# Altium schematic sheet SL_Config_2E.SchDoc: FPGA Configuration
size A; Organization: Altium Limited; Address1: L3, 12a Rodborough Rd; Address2: Frenchs Forest; Address3: NSW; Address4: Australia 2086; DocumentNumber: 2; SheetNumber: 2; SheetTotal: 5; Library Name: SpiritLevel_2E.SchLib
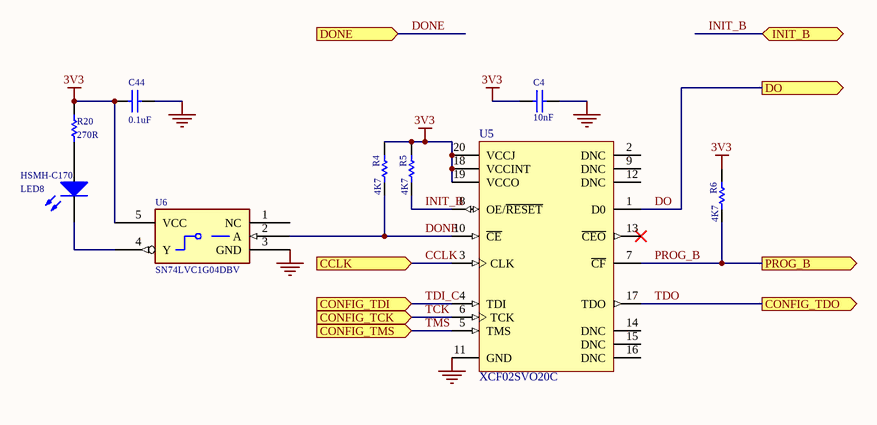
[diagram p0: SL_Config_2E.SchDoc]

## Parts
C4  10nF  [CC1608-0603]
C44  0.1uF  [CC2012-0805]
LED8  HSMH-C170  [SMD _LED]
R4  4K7  [CR2012-0805]
R5  4K7  [CR2012-0805]
R6  4K7  [CR2012-0805]
R20  270R  [CR2012-0805]
U5  XCF02SVO20C  [VO20]
U6  SN74LVC1G04DBV  [SO-G5/P.95]

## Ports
CCLK (in), CONFIG_TCK (in), CONFIG_TDI (in), CONFIG_TDO (out), CONFIG_TMS (in), DO (out), DONE (in), INIT_B (bidir), PROG_B (out)

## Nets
3V3: C4.1 C44.2 R4.1 R5.1 R6.1 R20.2 U5.18(VCCINT) U5.19(VCCO) U5.20(VCCJ) U6.5(VCC)
GND: C4.2 C44.1 U5.11(GND) U6.3(GND)
CCLK: U5.3(CLK) ; port CCLK
DO: U5.1(D0) ; port DO
DONE: R4.2 U5.10(~{CE}) U6.2(A) ; port DONE
INIT_B: R5.2 U5.8(OE/~{RESET}) ; port INIT_B
PROG_B: R6.2 U5.7(~{CF}) ; port PROG_B
TCK: U5.6(TCK) ; port CONFIG_TCK
TDI_C: U5.4(TDI) ; port CONFIG_TDI
TDO: U5.17(TDO) ; port CONFIG_TDO
TMS: U5.5(TMS) ; port CONFIG_TMS
NetLED8_1: LED8.1(A) R20.1
NetLED8_2: LED8.2(K) U6.4(Y)

Not connected (* = marked no-connect by the designer): U5 2(DNC) 9(DNC) 12(DNC) 13(~{CEO})* 14(DNC) 15(DNC) 16(DNC); U6 1(NC)

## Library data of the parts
C4 = CAP: Capacitor; AEMS Code: 2100341
C44 = CAP: Capacitor
LED8 = HSMX-C670: Typical RED GaAs SMD LED Agilent make; AEMS Code: 2610081
R4-R6 = RES: Resistor; AEMS Code: 1200226
R20 = RES: Resistor; AEMS Code: 1200430
U5 = XCF02SVO20C: XCF00S Series, Platform Flash In-System Programmable Configuration 3.3V PROM, 20-Pin TSOP, 2-Megabit, Commercial Grade; PackageDocument: ver1.0, May-2003; AEMS Code: CHANGED VALUE
U6 = SN74AHC1G04DBVR: Manufacturer: TI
